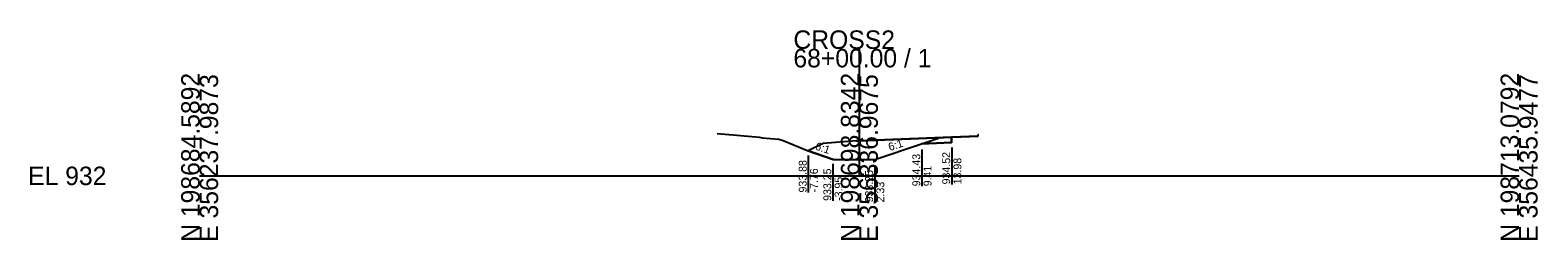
# Model space of a CAD drawing. Extents: x -26 to 203, y -10 to 14021.
# Drawn here: x -25.7 to 202.8, y 8990.3 to 9022.1 of the extents above; entities that cross this region are included whole.
import ezdxf

# ---------------------------------------------------------------- set-up
doc = ezdxf.new("R2010")
doc.units = 0
for name, color, linetype in [('Default', 7, 'Continuous'), ('P_E_XS_Ground', 7, 'Continuous'), ('P_XS', 7, 'Continuous'), ('P_XS_EAR_CommonGrnd', 7, 'Continuous'), ('P_XS_Lane', 7, 'Continuous'), ('P_XS_Rock', 7, 'Continuous')]:
    doc.layers.add(name, color=color, linetype=linetype)

msp = doc.modelspace()

# ---------------------------------------------------------------- linework, layer by layer
at = {"layer": 'Default'}
for p, q in [((100, 9000), (100, 9019.24)), ((0, 9000), (100, 9000)), ((100, 9000), (200, 9000))]:
    msp.add_line(p, q, dxfattribs=at)
at = {"layer": 'P_E_XS_Ground'}
for p, q in [((78.43, 9006.41), (81.43, 9006.17)), ((81.43, 9006.17), (81.97, 9006.1)), ((81.97, 9006.1), (84.84, 9005.85)), ((84.84, 9005.85), (85.26, 9005.77)), ((85.26, 9005.77), (87.81, 9005.56)), ((87.81, 9005.56), (88.44, 9005.34)), ((88.44, 9005.34), (92.24, 9003.77)), ((94.5, 9004.9), (92.24, 9003.77)), ((99.5, 9005.3), (94.5, 9004.9)), ((99.5, 9005.3), (100, 9005.32)), ((100, 9005.32), (117.98, 9006.04)), ((117.98, 9006.29), (118.06, 9006.29)), ((117.98, 9006.04), (117.98, 9006.29))]:
    msp.add_line(p, q, dxfattribs=at)
at = {"layer": 'P_XS'}
for p, q in [((109.41, 9004.86), (111.98, 9005.72)), ((113.98, 9005.88), (111.98, 9005.72)), ((117.98, 9006.04), (113.98, 9005.88))]:
    msp.add_line(p, q, dxfattribs=at)
at = {"layer": 'P_XS_EAR_CommonGrnd'}
msp.add_lwpolyline([(96.05, 9002.5), (102.33, 9002.5), (109.41, 9004.86), (113.98, 9005.04), (113.98, 9005.88), (100, 9005.32), (99.5, 9005.3), (94.5, 9004.9), (92.24, 9003.77)], close=True, dxfattribs=at)
at = {"layer": 'P_XS_Lane'}
for p, q in [((102.33, 9002.5), (109.41, 9004.86)), ((113.98, 9005.04), (109.41, 9004.86)), ((113.98, 9005.88), (113.98, 9005.04)), ((96.05, 9002.5), (92.24, 9003.77)), ((96.05, 9002.5), (102.33, 9002.5))]:
    msp.add_line(p, q, dxfattribs=at)
at = {"layer": 'P_XS_Rock'}
for p, q in [((114.01, 9004.3), (114.01, 8998.71)), ((92.26, 9003.07), (92.26, 8997.48)), ((109.48, 9004.01), (109.48, 8998.42)), ((95.99, 9001.8), (95.99, 8996.2)), ((102.32, 9001.58), (102.32, 8995.98))]:
    msp.add_line(p, q, dxfattribs=at)

# ---------------------------------------------------------------- texts
at = {"layer": 'Default'}
for s, p in [('CROSS2', (90, 9019.24)), ('68+00.00 / 1', (90, 9016.44)), ('EL 932', (-26, 8998.6))]:
    msp.add_text(s, height=2.8, dxfattribs=at).set_placement(p)
for s, p in [('N 198684.5892', (0, 8990)), ('E 356237.9873', (2.8, 8990)), ('N 198698.8342', (100, 8990)), ('E 356336.9675', (102.8, 8990)), ('N 198713.0792', (200, 8990)), ('E 356435.9477', (202.8, 8990))]:
    msp.add_text(s, height=2.8, rotation=90, dxfattribs=at).set_placement(p)
at = {"layer": 'P_XS_Rock'}
for s, rotation, p in [('6:1', 341.5651, (93.21, 9004.01)), ('6:1', 18.4349, (104.62, 9003.75)), ('933.88', 90, (92.01, 8997.48)), ('934.43', 90, (109.23, 8998.42)), ('934.52', 90, (113.76, 8998.71)), ('13.98', 90, (115.46, 8998.71)), ('-7.76', 90, (93.71, 8997.48)), ('933.25', 90, (95.74, 8996.21)), ('-3.95', 90, (97.44, 8996.21)), ('933.25', 90, (102.07, 8995.98)), ('9.41', 90, (110.93, 8998.42)), ('2.33', 90, (103.77, 8995.98))]:
    msp.add_text(s, height=1.2, rotation=rotation, dxfattribs=at).set_placement(p)

doc.saveas('drawing.dxf')
